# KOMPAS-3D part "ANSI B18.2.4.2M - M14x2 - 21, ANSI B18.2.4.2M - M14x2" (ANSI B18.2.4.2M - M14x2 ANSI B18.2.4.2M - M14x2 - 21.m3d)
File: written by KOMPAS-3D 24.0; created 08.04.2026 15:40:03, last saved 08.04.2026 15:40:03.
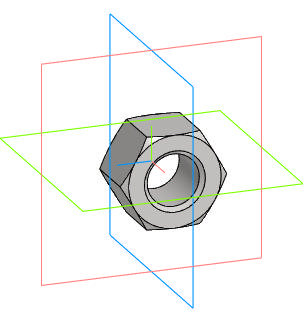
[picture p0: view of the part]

Document properties: Автор: R2D2; Полное имя файла: E:\Работа\Зайцев\VSO1121M-F-S Клапан запорный сальниковый DN.ru\DN15\исходные материалы\ANSI B18.2.4.2M - M14x2 ANSI B18.2.4.2M - M14x2 - 21.m3d

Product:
- Body: Solid1  | qty 1
- Part/product: ANSI B18.2.4.2M - M14x2 - 21  | designation ANSI B18.2.4.2M - M14x2
    Комментарий: Типы метрических   шестигранных гаек   2
    additional columns: Сталь, мягкая

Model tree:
1. Solid1  (labels: Solid1)

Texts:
  ANSI B18.2.4.2M - M14x2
